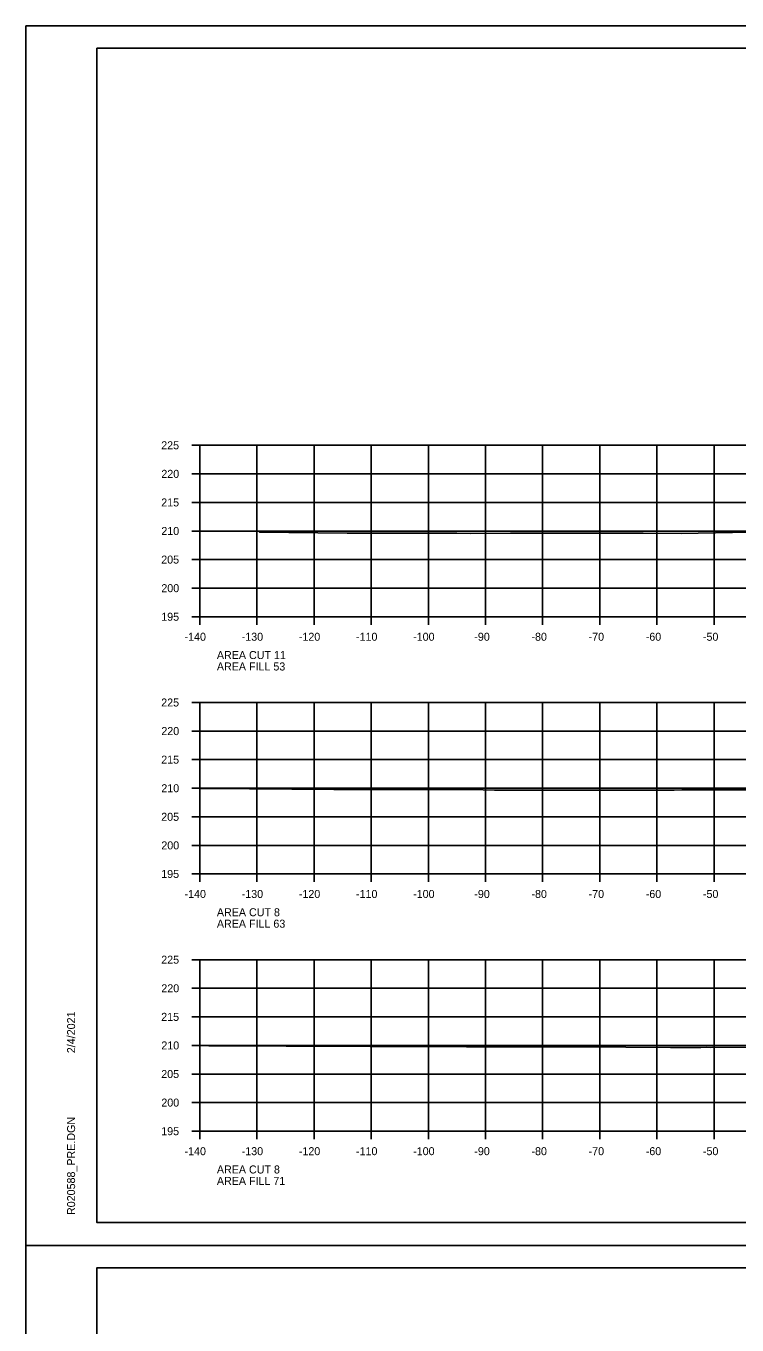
# Model space of a CAD drawing. Extents: x 1368968 to 1369915, y 377395 to 380381.
# Drawn here: x 1368967.7 to 1369092.1, y 378887.1 to 379114.4 of the extents above; entities that cross this region are included whole.
import ezdxf

# ---------------------------------------------------------------- set-up
doc = ezdxf.new("R2010")
doc.units = 0
for name, color, linetype in [('S_BREAKLINE_ANNOT', 7, 'Continuous'), ('S_BRIDGE', 7, 'Continuous'), ('S_BRIDGE_ANNOT', 7, 'Continuous'), ('S_CTL_TABLE', 7, 'Continuous'), ('S_DITCHLINE_ANNOT', 7, 'Continuous'), ('S_DROP_INLET', 7, 'Continuous')]:
    doc.layers.add(name, color=color, linetype=linetype)

msp = doc.modelspace()

# ---------------------------------------------------------------- linework, layer by layer
at = {"layer": 'S_BREAKLINE_ANNOT'}
for p, q in [((1368996.73, 379041.04), (1368998.13, 379041.04)), ((1368998.13, 379011.04), (1368998.13, 379041.04)), ((1368996.73, 379036.04), (1368998.13, 379036.04)), ((1368996.73, 379031.04), (1368998.13, 379031.04)), ((1368996.73, 379026.04), (1368998.13, 379026.04)), ((1368996.73, 379021.04), (1368998.13, 379021.04)), ((1368996.73, 379016.04), (1368998.13, 379016.04)), ((1368996.73, 379011.04), (1368998.13, 379011.04)), ((1368998.13, 379011.04), (1369278.13, 379011.04)), ((1368998.13, 379009.64), (1368998.13, 379011.04)), ((1369008.13, 379009.64), (1369008.13, 379011.04)), ((1369018.13, 379009.64), (1369018.13, 379011.04)), ((1369028.13, 379009.64), (1369028.13, 379011.04)), ((1369038.13, 379009.64), (1369038.13, 379011.04)), ((1369048.13, 379009.64), (1369048.13, 379011.04)), ((1369058.13, 379009.64), (1369058.13, 379011.04)), ((1369068.13, 379009.64), (1369068.13, 379011.04)), ((1369078.13, 379009.64), (1369078.13, 379011.04)), ((1369088.13, 379009.64), (1369088.13, 379011.04)), ((1368996.73, 378996.04), (1368998.13, 378996.04)), ((1368998.13, 378966.04), (1368998.13, 378996.04)), ((1368996.73, 378991.04), (1368998.13, 378991.04)), ((1368996.73, 378986.04), (1368998.13, 378986.04)), ((1368996.73, 378981.04), (1368998.13, 378981.04)), ((1368996.73, 378976.04), (1368998.13, 378976.04)), ((1368996.73, 378971.04), (1368998.13, 378971.04)), ((1368996.73, 378966.04), (1368998.13, 378966.04)), ((1368998.13, 378966.04), (1369278.13, 378966.04)), ((1368998.13, 378964.64), (1368998.13, 378966.04)), ((1369008.13, 378964.64), (1369008.13, 378966.04)), ((1369018.13, 378964.64), (1369018.13, 378966.04)), ((1369028.13, 378964.64), (1369028.13, 378966.04)), ((1369038.13, 378964.64), (1369038.13, 378966.04)), ((1369048.13, 378964.64), (1369048.13, 378966.04)), ((1369058.13, 378964.64), (1369058.13, 378966.04)), ((1369068.13, 378964.64), (1369068.13, 378966.04)), ((1369078.13, 378964.64), (1369078.13, 378966.04)), ((1369088.13, 378964.64), (1369088.13, 378966.04)), ((1368996.73, 378951.04), (1368998.13, 378951.04)), ((1368998.13, 378921.04), (1368998.13, 378951.04)), ((1368996.73, 378946.04), (1368998.13, 378946.04)), ((1368996.73, 378941.04), (1368998.13, 378941.04)), ((1368996.73, 378936.04), (1368998.13, 378936.04)), ((1368996.73, 378931.04), (1368998.13, 378931.04)), ((1368996.73, 378926.04), (1368998.13, 378926.04)), ((1368996.73, 378921.04), (1368998.13, 378921.04)), ((1368998.13, 378921.04), (1369278.13, 378921.04)), ((1368998.13, 378919.64), (1368998.13, 378921.04)), ((1369008.13, 378919.64), (1369008.13, 378921.04)), ((1369018.13, 378919.64), (1369018.13, 378921.04)), ((1369028.13, 378919.64), (1369028.13, 378921.04)), ((1369038.13, 378919.64), (1369038.13, 378921.04)), ((1369048.13, 378919.64), (1369048.13, 378921.04)), ((1369058.13, 378919.64), (1369058.13, 378921.04)), ((1369068.13, 378919.64), (1369068.13, 378921.04)), ((1369078.13, 378919.64), (1369078.13, 378921.04)), ((1369088.13, 378919.64), (1369088.13, 378921.04))]:
    msp.add_line(p, q, dxfattribs=at)
at = {"layer": 'S_BRIDGE_ANNOT'}
for p, q in [((1368980.13, 379110.5), (1369296.31, 379110.5)), ((1368980.13, 378905.04), (1368980.13, 379110.5)), ((1368980.13, 378905.04), (1368980.13, 378905.04)), ((1369296.31, 378905.04), (1368980.13, 378905.04)), ((1368980.13, 378897.16), (1369296.31, 378897.16)), ((1368980.13, 378691.7), (1368980.13, 378897.16))]:
    msp.add_line(p, q, dxfattribs=at)
at = {"layer": 'S_CTL_TABLE'}
for points in [[(1369008.6, 379026.03), (1369008.61, 379025.81), (1369023.93, 379025.69), (1369029.38, 379025.67), (1369043.1, 379025.66), (1369045.57, 379025.59), (1369052.52, 379025.64), (1369060.61, 379025.66), (1369067.19, 379025.64), (1369075.72, 379025.64), (1369082.38, 379025.62), (1369097.38, 379025.88)], [(1368998.13, 378980.99), (1368999.5, 378980.99), (1369021.57, 378980.82), (1369022.69, 378980.82), (1369045.45, 378980.82), (1369045.63, 378980.82), (1369045.72, 378980.82), (1369049.73, 378980.68), (1369050.26, 378980.68), (1369058.8, 378980.7), (1369064.52, 378980.71), (1369064.85, 378980.71), (1369080.69, 378980.71), (1369081.15, 378980.71), (1369082.51, 378980.73), (1369091.59, 378980.75), (1369098.13, 378980.78)], [(1368999.7, 378935.95), (1369000.3, 378935.97), (1369013.25, 378935.94), (1369015.81, 378935.91), (1369027.94, 378935.86), (1369037.55, 378935.83), (1369044.82, 378935.81), (1369048.81, 378935.81), (1369054.77, 378935.78), (1369064.75, 378935.81), (1369069.2, 378935.78), (1369070.2, 378935.78), (1369070.28, 378935.78), (1369072.71, 378935.75), (1369080.49, 378935.67), (1369085.78, 378935.7), (1369086.78, 378935.71), (1369087.48, 378935.7), (1369087.77, 378935.71), (1369099.98, 378935.64)]]:
    msp.add_lwpolyline(points, dxfattribs=at)
at = {"layer": 'S_DITCHLINE_ANNOT'}
for p, q in [((1368998.13, 379041.04), (1369278.13, 379041.04)), ((1368998.13, 379011.04), (1368998.13, 379041.04)), ((1369008.13, 379011.04), (1369008.13, 379041.04)), ((1369018.13, 379011.04), (1369018.13, 379041.04)), ((1369028.13, 379011.04), (1369028.13, 379041.04)), ((1369038.13, 379011.04), (1369038.13, 379041.04)), ((1369048.13, 379011.04), (1369048.13, 379041.04)), ((1369058.13, 379011.04), (1369058.13, 379041.04)), ((1369068.13, 379011.04), (1369068.13, 379041.04)), ((1369078.13, 379011.04), (1369078.13, 379041.04)), ((1369088.13, 379011.04), (1369088.13, 379041.04)), ((1368998.13, 379036.04), (1369278.13, 379036.04)), ((1368998.13, 379031.04), (1369278.13, 379031.04)), ((1368998.13, 379026.04), (1369278.13, 379026.04)), ((1368998.13, 379021.04), (1369278.13, 379021.04)), ((1368998.13, 379016.04), (1369278.13, 379016.04)), ((1368998.13, 379011.04), (1369278.13, 379011.04)), ((1368998.13, 378996.04), (1369278.13, 378996.04)), ((1368998.13, 378966.04), (1368998.13, 378996.04)), ((1369008.13, 378966.04), (1369008.13, 378996.04)), ((1369018.13, 378966.04), (1369018.13, 378996.04)), ((1369028.13, 378966.04), (1369028.13, 378996.04)), ((1369038.13, 378966.04), (1369038.13, 378996.04)), ((1369048.13, 378966.04), (1369048.13, 378996.04)), ((1369058.13, 378966.04), (1369058.13, 378996.04)), ((1369068.13, 378966.04), (1369068.13, 378996.04)), ((1369078.13, 378966.04), (1369078.13, 378996.04)), ((1369088.13, 378966.04), (1369088.13, 378996.04)), ((1368998.13, 378991.04), (1369278.13, 378991.04)), ((1368998.13, 378986.04), (1369278.13, 378986.04)), ((1368998.13, 378981.04), (1369278.13, 378981.04)), ((1368998.13, 378976.04), (1369278.13, 378976.04)), ((1368998.13, 378971.04), (1369278.13, 378971.04)), ((1368998.13, 378966.04), (1369278.13, 378966.04)), ((1368998.13, 378951.04), (1369278.13, 378951.04)), ((1368998.13, 378921.04), (1368998.13, 378951.04)), ((1369008.13, 378921.04), (1369008.13, 378951.04)), ((1369018.13, 378921.04), (1369018.13, 378951.04)), ((1369028.13, 378921.04), (1369028.13, 378951.04)), ((1369038.13, 378921.04), (1369038.13, 378951.04)), ((1369048.13, 378921.04), (1369048.13, 378951.04)), ((1369058.13, 378921.04), (1369058.13, 378951.04)), ((1369068.13, 378921.04), (1369068.13, 378951.04)), ((1369078.13, 378921.04), (1369078.13, 378951.04)), ((1369088.13, 378921.04), (1369088.13, 378951.04)), ((1368998.13, 378946.04), (1369278.13, 378946.04)), ((1368998.13, 378941.04), (1369278.13, 378941.04)), ((1368998.13, 378936.04), (1369278.13, 378936.04)), ((1368998.13, 378931.04), (1369278.13, 378931.04)), ((1368998.13, 378926.04), (1369278.13, 378926.04)), ((1368998.13, 378921.04), (1369278.13, 378921.04))]:
    msp.add_line(p, q, dxfattribs=at)
at = {"layer": 'S_DROP_INLET'}
for p, q in [((1368967.73, 379114.4), (1369301.07, 379114.4)), ((1368967.73, 378901.06), (1369301.07, 378901.06)), ((1368967.73, 378901.06), (1369301.07, 378901.06))]:
    msp.add_line(p, q, dxfattribs=at)
for points in [[(1368967.73, 379114.4), (1369301.07, 379114.4), (1369301.07, 378901.06), (1368967.73, 378901.06)], [(1369214.05, 379110.5), (1369214.05, 379100.62), (1369249.79, 379100.62), (1369249.79, 379097.7), (1369272.99, 379097.7), (1369272.99, 379073.37), (1369296.31, 379073.37), (1369296.31, 378905.04), (1368980.13, 378905.04), (1368980.13, 379110.5)], [(1368967.73, 378901.06), (1369301.07, 378901.06), (1369301.07, 378687.72), (1368967.73, 378687.72)], [(1369214.05, 378897.16), (1369214.05, 378887.28), (1369249.79, 378887.28), (1369249.79, 378884.36), (1369272.99, 378884.36), (1369272.99, 378860.03), (1369296.31, 378860.03), (1369296.31, 378691.7), (1368980.13, 378691.7), (1368980.13, 378897.16)]]:
    msp.add_lwpolyline(points, close=True, dxfattribs=at)

# ---------------------------------------------------------------- texts
at = {"layer": 'S_BRIDGE'}
for s, p in [('225', (1368991.39, 379040.34)), ('220', (1368991.41, 379035.34)), ('215', (1368991.39, 379030.34)), ('210', (1368991.41, 379025.34)), ('205', (1368991.39, 379020.34)), ('200', (1368991.41, 379015.34)), ('195', (1368991.39, 379010.34)), ('-140', (1368995.47, 379006.84)), ('-130', (1369005.47, 379006.84)), ('-120', (1369015.47, 379006.84)), ('-110', (1369025.47, 379006.84)), ('-100', (1369035.47, 379006.84)), ('-90', (1369046.17, 379006.84)), ('-80', (1369056.17, 379006.84)), ('-70', (1369066.17, 379006.84)), ('-60', (1369076.17, 379006.84)), ('-50', (1369086.17, 379006.84)), ('AREA CUT 11', (1369001.13, 379003.64)), ('AREA FILL 53', (1369001.13, 379001.64)), ('225', (1368991.39, 378995.34)), ('220', (1368991.41, 378990.34)), ('215', (1368991.39, 378985.34)), ('210', (1368991.41, 378980.34)), ('205', (1368991.39, 378975.34)), ('200', (1368991.41, 378970.34)), ('195', (1368991.39, 378965.34)), ('-140', (1368995.47, 378961.84)), ('-130', (1369005.47, 378961.84)), ('-120', (1369015.47, 378961.84)), ('-110', (1369025.47, 378961.84)), ('-100', (1369035.47, 378961.84)), ('-90', (1369046.17, 378961.84)), ('-80', (1369056.17, 378961.84)), ('-70', (1369066.17, 378961.84)), ('-60', (1369076.17, 378961.84)), ('-50', (1369086.17, 378961.84)), ('AREA CUT 8', (1369001.13, 378958.64)), ('AREA FILL 63', (1369001.13, 378956.64)), ('225', (1368991.39, 378950.34)), ('220', (1368991.41, 378945.34)), ('215', (1368991.39, 378940.34)), ('210', (1368991.41, 378935.34)), ('205', (1368991.39, 378930.34)), ('200', (1368991.41, 378925.34)), ('195', (1368991.39, 378920.34)), ('-140', (1368995.47, 378916.84)), ('-130', (1369005.47, 378916.84)), ('-120', (1369015.47, 378916.84)), ('-110', (1369025.47, 378916.84)), ('-100', (1369035.47, 378916.84)), ('-90', (1369046.17, 378916.84)), ('-80', (1369056.17, 378916.84)), ('-70', (1369066.17, 378916.84)), ('-60', (1369076.17, 378916.84)), ('-50', (1369086.17, 378916.84)), ('AREA CUT 8', (1369001.13, 378913.64)), ('AREA FILL 71', (1369001.13, 378911.64))]:
    msp.add_text(s, height=1.4, dxfattribs=at).set_placement(p)
at = {"layer": 'S_BRIDGE_ANNOT'}
for s, p in [('2/4/2021', (1368976.32, 378934.69)), ('R020588_PRE.DGN', (1368976.32, 378906.37))]:
    msp.add_text(s, height=1.4, rotation=90, dxfattribs=at).set_placement(p)

doc.saveas('drawing.dxf')
